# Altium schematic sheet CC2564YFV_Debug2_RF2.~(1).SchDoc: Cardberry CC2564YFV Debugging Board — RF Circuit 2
size A4; DrawnBy: Pavel Ivshin; Engineer: Pavel Ivshin; Organization: Cardberry; Revision: 0; SheetNumber: 2; SheetTotal: 4
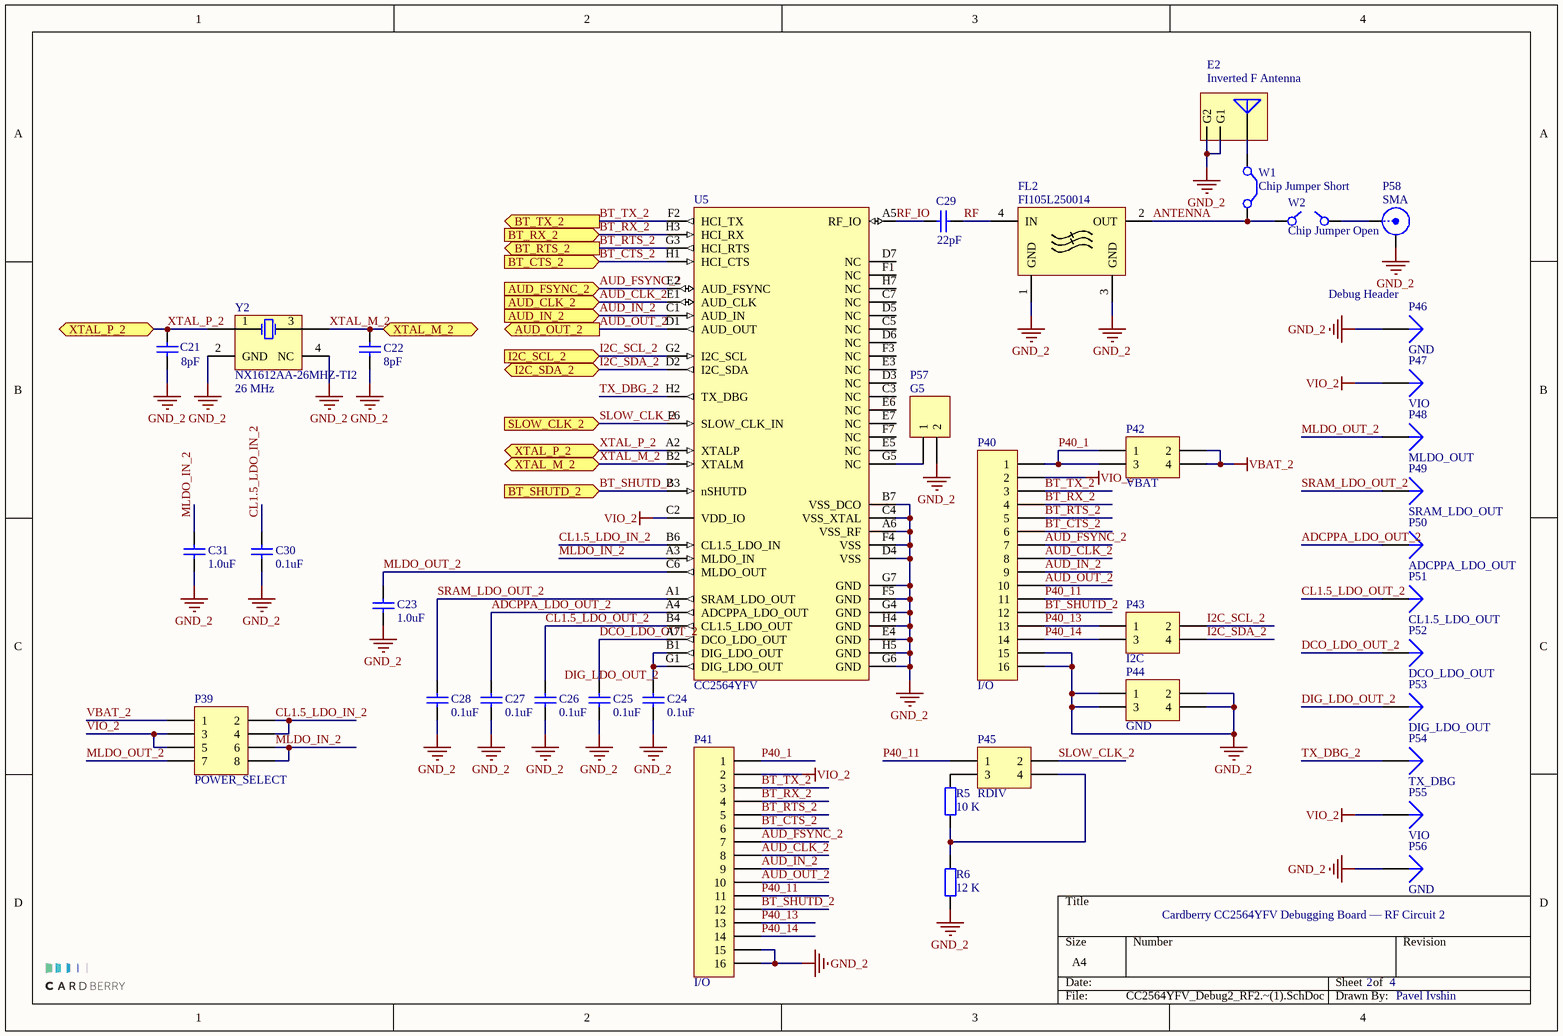
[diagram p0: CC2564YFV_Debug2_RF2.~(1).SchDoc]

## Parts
C21  value 8pF  [0402]  (hidden comment: Cap Semi 8 pF)
C22  value 8pF  [0402]  (hidden comment: Cap Semi 8 pF)
C23  value 1.0uF  [0402]  (hidden comment: C1005X5R1A105K050BB)
C24  value 0.1uF  [0402]  (hidden comment: C1005X7R1H104M050BB)
C25  value 0.1uF  [0402]  (hidden comment: C1005X7R1H104M050BB)
C26  value 0.1uF  [0402]  (hidden comment: C1005X7R1H104M050BB)
C27  value 0.1uF  [0402]  (hidden comment: C1005X7R1H104M050BB)
C28  value 0.1uF  [0402]  (hidden comment: C1005X7R1H104M050BB)
C29  value 22pF  [1-0201]  (hidden comment: GRM0335C1E220JA01D)
C30  value 0.1uF  [0402]  (hidden comment: C1005X7R1H104M050BB)
C31  value 1.0uF  [0402]  (hidden comment: C1005X5R1A105K050BB)
E2  Inverted F Antenna  [Inverted_F_Antenna]
FL2  FI105L250014  [FL105_Electrodes]
P39  POWER_SELECT  [HDR2X4]
P40  I/O  [HDR1X16]
P41  I/O  [HDR1X16]
P42  VBAT  [HDR2X2]
P43  I2C  [HDR2X2]
P44  GND  [HDR2X2]
P45  RDIV  [HDR2X2]
P46  GND  [PIN1]
P47  VIO  [PIN1]
P48  MLDO_OUT  [PIN1]
P49  SRAM_LDO_OUT  [PIN1]
P50  ADCPPA_LDO_OUT  [PIN1]
P51  CL1.5_LDO_OUT  [PIN1]
P52  DCO_LDO_OUT  [PIN1]
P53  DIG_LDO_OUT  [PIN1]
P54  TX_DBG  [PIN1]
P55  VIO  [PIN1]
P56  GND  [PIN1]
P57  G5  [HDR1X2]
P58  SMA  [SMA]
R5  value 10 K  [3-0603]  (hidden comment: Res Chip 10 K)
R6  value 12 K  [3-0603]  (hidden comment: Res Chip 12 K)
U5  CC2564YFV  [YFV (R-XBGA-N54)]
W1  Chip Jumper Short  [2-0402]
W2  Chip Jumper Open  [2-0402]
Y2  NX1612AA-26MHZ-TI2  value 26 MHz  [XTAL_QUAD_1.6x1.2mm]

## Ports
AUD_CLK_2 (in), AUD_FSYNC_2 (in), AUD_IN_2 (in), AUD_OUT_2 (out), BT_CTS_2 (in), BT_RTS_2 (out), BT_RX_2 (in), BT_SHUTD_2 (in), BT_TX_2 (out), I2C_SCL_2 (in), I2C_SDA_2 (bidir), SLOW_CLK_2 (in), XTAL_M_2 (bidir), XTAL_P_2 (bidir)

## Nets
GND_2: C21.1 C22.1 C23.1 C24.1 C25.1 C26.1 C27.1 C28.1 C30.1 C31.1 E2.2(G1) E2.3(G2) FL2.1(GND) FL2.3(GND) P40.15 P40.16 P41.15 P41.16 P44.1 P44.2 P44.3 P44.4 P46.1 P56.1 P57.2 P58.2(Y) R6.1 U5.A6(VSS_RF) U5.B7(VSS_DCO) U5.C4(VSS_XTAL) U5.D4(VSS) U5.E4(GND) U5.F4(VSS) U5.F5(GND) U5.G4(GND) U5.G6(GND) U5.G7(GND) U5.H4(GND) U5.H5(GND) Y2.2(GND) Y2.4(NC)
VBAT_2: P39.1 P42.2 P42.4
VIO_2: P39.3 P39.5 P40.2 P41.2 P47.1 P55.1 U5.C2(VDD_IO)
ADCPPA_LDO_OUT_2: C27.2 P50.1 U5.A4(ADCPPA_LDO_OUT)
ANTENNA: FL2.2(OUT) W1.2(C2) W2.1(C1)
AUD_CLK_2: P40.8 P41.8 U5.E1(AUD_CLK) ; port AUD_CLK_2
AUD_FSYNC_2: P40.7 P41.7 U5.E2(AUD_FSYNC) ; port AUD_FSYNC_2
AUD_IN_2: P40.9 P41.9 U5.C1(AUD_IN) ; port AUD_IN_2
AUD_OUT_2: P40.10 P41.10 U5.D1(AUD_OUT) ; port AUD_OUT_2
BT_CTS_2: P40.6 P41.6 U5.H1(HCI_CTS) ; port BT_CTS_2
BT_RTS_2: P40.5 P41.5 U5.G3(HCI_RTS) ; port BT_RTS_2
BT_RX_2: P40.4 P41.4 U5.H3(HCI_RX) ; port BT_RX_2
BT_SHUTD_2: P40.12 P41.12 U5.B3(nSHUTD) ; port BT_SHUTD_2
BT_TX_2: P40.3 P41.3 U5.F2(HCI_TX) ; port BT_TX_2
CL1.5_LDO_IN_2: C30.2 P39.2 P39.4 U5.B6(CL1.5_LDO_IN)
CL1.5_LDO_OUT_2: C26.2 P51.1 U5.B4(CL1.5_LDO_OUT)
DCO_LDO_OUT_2: C25.2 P52.1 U5.A7(DCO_LDO_OUT)
DIG_LDO_OUT_2: C24.2 P53.1 U5.B1(DIG_LDO_OUT) U5.G1(DIG_LDO_OUT)
I2C_SCL_2: P43.2 U5.G2(I2C_SCL) ; port I2C_SCL_2
I2C_SDA_2: P43.4 U5.D2(I2C_SDA) ; port I2C_SDA_2
MLDO_IN_2: C31.2 P39.6 P39.8 U5.A3(MLDO_IN)
MLDO_OUT_2: C23.2 P39.7 P48.1 U5.C6(MLDO_OUT)
P40_1: P40.1 P41.1 P42.1 P42.3
P40_11: P40.11 P41.11 P45.1
P40_13: P40.13 P41.13 P43.1
P40_14: P40.14 P41.14 P43.3
RF: C29.2 FL2.4(IN)
RF_IO: C29.1 U5.A5(RF_IO)
SLOW_CLK_2: P45.2 U5.F6(SLOW_CLK_IN) ; port SLOW_CLK_2
SRAM_LDO_OUT_2: C28.2 P49.1 U5.A1(SRAM_LDO_OUT)
TX_DBG_2: P54.1 U5.H2(TX_DBG)
XTAL_M_2: C22.2 U5.B2(XTALM) Y2.3(OSC2) ; port XTAL_M_2
XTAL_P_2: C21.2 U5.A2(XTALP) Y2.1(OSC1) ; port XTAL_P_2
NetE2_1: E2.1(FEED) W1.1(C1)
NetP45_3: P45.3 R5.2
NetP45_4: P45.4 R5.1 R6.2
NetP57_1: P57.1 U5.G5(NC)
NetP58_1: P58.1(X) W2.2(C2)

Not connected (* = marked no-connect by the designer): U5 C3(NC) C5(NC) C7(NC) D3(NC) D5(NC) D6(NC) D7(NC) E3(NC) E5(NC) E6(NC) E7(NC) F1(NC) F3(NC) F7(NC) H7(NC)

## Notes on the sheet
- (near P46) Debug Header

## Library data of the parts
C21 C22 = Cap Semi 8 pF: Chip Capacitor, 8 pF
C23 C31 = C1005X5R1A105K050BB: 1.0 uF/10 V 0402
C24-C28 C30 = C1005X7R1H104M050BB: 0.1 uF/50 V 0402
C29 = GRM0335C1E220JA01D: 22 pF/25 V 0201
E2 = Inverted F Antenna: Inverted F Antenna (Design Note DN0007; SWRU120B)
FL2 = FI105L250014: 2.4 GHz Low Pass Filter
P39 = Header 4X2: Header, 4-Pin, Dual row
P40 P41 = Header 16: Header, 16-Pin
P42-P45 = Header 2X2: Header, 2-Pin, Dual row
P46-P56 = Plug
P57 = Header 2: Header, 2-Pin
P58 = SMA: SMA Generic Connector
R5 = Res Chip 10 K: Chip Resistor, 10 K
R6 = Res Chip 12 K: Chip Resistor, 12 K
U5 = CC2564YFV: CC2564, 54-balls DSBGA
Y2 = NX1612AA-26MHZ-TI2: Crystal Oscillator 26 MHz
